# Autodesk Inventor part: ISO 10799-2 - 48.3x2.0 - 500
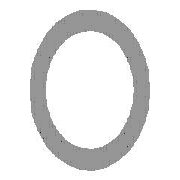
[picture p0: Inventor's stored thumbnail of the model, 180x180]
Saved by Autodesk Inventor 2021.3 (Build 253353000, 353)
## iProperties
_CCFamilyMember: 14
_CCFamilyDisplayName: ISO 10799-2 (Profils creux circulaires - Formés à froid) - Aciers de construction - Coupes creuses profilées formées à froid, soudées
_FrameMemberDoc: Frame Member File
_Version: 25.0.0
_GetPNFromCC: 1
IsCustomPart: 1
Created: 2018-01
Part Number: ISO 10799-2 - 48.3x2.0 - 500
Material: Acier, doux
Description: Aciers de construction - Coupes creuses profilées formées à froid, soudées
Document SubType Name: Modeling
Standard: ISO
Designer: Fabian Perrée
Standard Revision: First edition 2011-09-15
Standards Organization: ISO
Language: fr-FR
Size Designation: 48.3x2.0
Categories: <MemberInstance><Categories><Category DisplayName="Profilés" InternalName="089c4875-fa83-4c05-b084-43b9cc11f5ed" Mnemonic="GRDR"><CategoryParameter DisplayName=
Stock Number: 48.3x2.0
Density: 7.85 g/cm^3
Appearance: Semi-poli
Mass: 1065.61 g
Surface Area: 1369.22 cm^2
Volume: 135.746 cm^3
G_L: 500,000 mm
G_W: 48,300 mm
G_H: 48,300 mm
+2D9F7695-4A5C-463C-B0A0-518010C687B0+DETAILDECOUPE1: Grugeage
+B9C4214B-9881-441A-A920-C25C553D1DF1+DETAILDECOUPE2: Grugeage
Author: Fabian Perrée
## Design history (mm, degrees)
node "Plan de départ"
node "Plan de fin"
sketch "Esquisse"
  geometry: C1 r 22.15 at (0, 0); C2 r 24.15 at (0, 0); 2 further points
  constraints: 3 coincident, 2 centre point
  dimensions: "d0" = 48.3 diameter of C2 (= G_H); "d1" = 2 radial gap between concentric circles of C2 C1 (= G_T)
extrude "Corps" new body sketch "Esquisse" stored distance "d2" = 500 (= G_L); taper "d3" = 0 deg
node "Driven Length"
  sketch "Sketch3"
    geometry: L1 (0, 0)-(10, 0) reference
    constraints: 2 end point, 1 horizontal
  workplane "Work Plane3"
  sketch "Sketch4"
    geometry: L1 (-2, 0)-(12, 0) reference; L2 (-2, 500)-(12, 500) reference
    dimensions: "d7" = 500 distance between parallel lines of L1 L2 (derived)
body "Solid1"
feature "Sculpter1"
feature "Combiner1"
feature "Sculpter3"
feature "Combiner3"
body "Srf29"
body "Srf30"
node "Solide11"
body "Srf32"
body "Srf33"
node "Solide12"
feature "Surface1"
body "Srf28"
feature "Carreau délimité19" dims "d44" = 5, "d45" = 0
feature "Carreau délimité20" dims "d46" = 5, "d47" = 0
feature "Surface3"
body "Srf31"
feature "Carreau délimité21" dims "d48" = 5, "d49" = 0
feature "Carreau délimité22" dims "d50" = 5, "d51" = 0
other parameters: "G_H" = 48.3 [user parameter; used in 1 equation term], "G_T" = 2 [user parameter; used in 1 equation term], "G_L" = 500 (= d7) [user parameter; used in 1 equation term], "G_OFFSET_START" = 0 [user parameter; used in 1 equation term], "G_OFFSET_END" = 0 [user parameter; used in 1 equation term], "d4" = 0 (computed from G_OFFSET_START), "d5" = 500 (= G_OFFSET_END + B_L), "B_L" = 500 [user parameter; used in 1 equation term], "d6" = 90 deg, "MAS" = 0.228 [user parameter]
